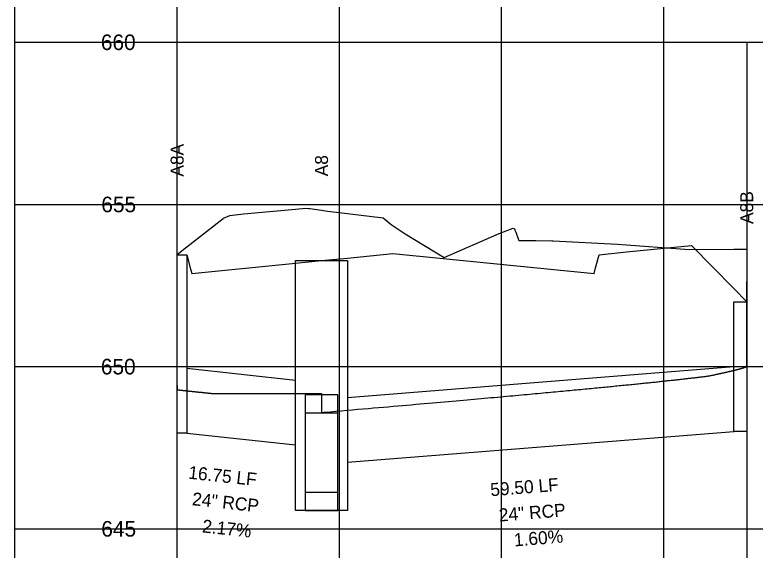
# Model space of a CAD drawing. Extents: x 2252703 to 2264864, y 13787568 to 13790989.
# Drawn here: x 2264413.7 to 2264527.7, y 13788382.5 to 13788465 of the extents above; entities that cross this region are included whole.
import ezdxf

# ---------------------------------------------------------------- set-up
doc = ezdxf.new("R2010")
doc.units = 0
for name, color, linetype in [('blank4', 7, 'Continuous'), ('BORD_grid_bottom_major_5int', 7, 'Continuous'), ('D_DRN_PROF_HGL', 7, 'Continuous'), ('D_PROF_1', 7, 'Continuous'), ('D_PROF_NOTES_1', 7, 'Continuous'), ('Default', 7, 'Continuous'), ('Drain_PipeInside', 7, 'Continuous'), ('E_Terrain', 7, 'Continuous'), ('Inlet', 7, 'Continuous'), ('z - Construction', 7, 'Continuous')]:
    doc.layers.add(name, color=color, linetype=linetype)

msp = doc.modelspace()

# ---------------------------------------------------------------- linework, layer by layer
at = {"layer": 'blank4'}
msp.add_lwpolyline([(2264438.67, 13788360.79), (2264438.67, 13788460.79), (2264526.42, 13788460.79), (2264526.42, 13788360.79)], close=True, dxfattribs=at)
at = {"layer": 'BORD_grid_bottom_major_5int'}
for p, q in [((2264413.67, 13788310.79), (2264413.67, 13788610.79)), ((2264438.67, 13788310.79), (2264438.67, 13788610.79)), ((2264463.67, 13788310.79), (2264463.67, 13788610.79)), ((2264488.67, 13788310.79), (2264488.67, 13788610.79)), ((2264513.67, 13788310.79), (2264513.67, 13788610.79)), ((2264413.67, 13788460.79), (2264763.67, 13788460.79)), ((2264413.67, 13788435.79), (2264763.67, 13788435.79)), ((2264413.67, 13788410.79), (2264763.67, 13788410.79)), ((2264413.67, 13788385.79), (2264763.67, 13788385.79))]:
    msp.add_line(p, q, dxfattribs=at)
at = {"layer": 'D_DRN_PROF_HGL'}
msp.add_line((2264460.92, 13788406.67), (2264460.92, 13788403.73), dxfattribs=at)
for points in [[(2264460.92, 13788403.73), (2264461.33, 13788403.76), (2264462.24, 13788403.84), (2264463.13, 13788403.92), (2264464, 13788403.99), (2264464.86, 13788404.07), (2264465.7, 13788404.14), (2264466.53, 13788404.21), (2264467.34, 13788404.28), (2264468.14, 13788404.35), (2264468.93, 13788404.42), (2264469.7, 13788404.48), (2264470.46, 13788404.55), (2264471.2, 13788404.61), (2264471.94, 13788404.68), (2264472.66, 13788404.74), (2264473.37, 13788404.8), (2264474.06, 13788404.86), (2264474.75, 13788404.92), (2264475.43, 13788404.98), (2264476.09, 13788405.04), (2264476.75, 13788405.1), (2264477.39, 13788405.15), (2264478.03, 13788405.21), (2264478.65, 13788405.27), (2264479.27, 13788405.32), (2264479.88, 13788405.37), (2264480.47, 13788405.43), (2264481.06, 13788405.48), (2264481.64, 13788405.53), (2264482.22, 13788405.58), (2264482.78, 13788405.63), (2264483.34, 13788405.68), (2264483.89, 13788405.73), (2264484.43, 13788405.78), (2264484.96, 13788405.82), (2264485.49, 13788405.87), (2264486, 13788405.92), (2264486.52, 13788405.96), (2264487.02, 13788406.01), (2264487.52, 13788406.05), (2264488.01, 13788406.1), (2264488.49, 13788406.14), (2264488.97, 13788406.19), (2264489.44, 13788406.23), (2264489.91, 13788406.27), (2264490.37, 13788406.31), (2264490.82, 13788406.35), (2264491.27, 13788406.39), (2264491.72, 13788406.44), (2264492.15, 13788406.48), (2264492.58, 13788406.51), (2264493.01, 13788406.55), (2264493.43, 13788406.59), (2264493.85, 13788406.63), (2264494.26, 13788406.67), (2264494.66, 13788406.71), (2264495.06, 13788406.74), (2264495.46, 13788406.78), (2264495.85, 13788406.82), (2264496.23, 13788406.85), (2264496.62, 13788406.89), (2264496.99, 13788406.92), (2264497.36, 13788406.96), (2264497.73, 13788406.99), (2264498.1, 13788407.03), (2264498.46, 13788407.06), (2264498.81, 13788407.09), (2264499.16, 13788407.13), (2264499.51, 13788407.16), (2264499.85, 13788407.19), (2264500.19, 13788407.22), (2264500.52, 13788407.26), (2264500.86, 13788407.29), (2264501.18, 13788407.32), (2264501.51, 13788407.35), (2264501.83, 13788407.38), (2264502.14, 13788407.41), (2264502.46, 13788407.44), (2264502.77, 13788407.47), (2264503.07, 13788407.5), (2264503.37, 13788407.53), (2264503.67, 13788407.56), (2264503.97, 13788407.59), (2264504.26, 13788407.61), (2264504.55, 13788407.64), (2264504.83, 13788407.67), (2264505.12, 13788407.7), (2264505.4, 13788407.72), (2264505.67, 13788407.75), (2264505.95, 13788407.78), (2264506.22, 13788407.81), (2264506.49, 13788407.83), (2264506.75, 13788407.86), (2264507.01, 13788407.88), (2264507.27, 13788407.91), (2264507.53, 13788407.94), (2264507.78, 13788407.96), (2264508.03, 13788407.99), (2264508.28, 13788408.01), (2264508.52, 13788408.03), (2264508.77, 13788408.06), (2264509.01, 13788408.08), (2264509.24, 13788408.11), (2264509.48, 13788408.13), (2264509.71, 13788408.15), (2264509.94, 13788408.18), (2264510.17, 13788408.2), (2264510.39, 13788408.22), (2264510.61, 13788408.25), (2264510.84, 13788408.27), (2264511.05, 13788408.29), (2264511.27, 13788408.31), (2264511.48, 13788408.34), (2264511.69, 13788408.36), (2264511.9, 13788408.38), (2264512.11, 13788408.4), (2264512.31, 13788408.42), (2264512.51, 13788408.44), (2264512.71, 13788408.47), (2264512.91, 13788408.49), (2264513.11, 13788408.51), (2264513.3, 13788408.53), (2264513.49, 13788408.55), (2264513.68, 13788408.57), (2264513.87, 13788408.59), (2264514.05, 13788408.61), (2264514.24, 13788408.63), (2264514.42, 13788408.65), (2264514.6, 13788408.67), (2264514.78, 13788408.69), (2264514.95, 13788408.7), (2264515.13, 13788408.72), (2264515.3, 13788408.74), (2264515.47, 13788408.76), (2264515.64, 13788408.78), (2264515.8, 13788408.8), (2264515.97, 13788408.82), (2264516.13, 13788408.83), (2264516.29, 13788408.85), (2264516.45, 13788408.87), (2264516.61, 13788408.89), (2264516.76, 13788408.9), (2264516.92, 13788408.92), (2264517.07, 13788408.94), (2264517.22, 13788408.96), (2264517.37, 13788408.97), (2264517.52, 13788408.99), (2264517.67, 13788409.01), (2264517.81, 13788409.02), (2264517.95, 13788409.04), (2264518.09, 13788409.06), (2264518.23, 13788409.07), (2264518.37, 13788409.09), (2264518.51, 13788409.1), (2264518.64, 13788409.12), (2264518.78, 13788409.14), (2264518.91, 13788409.15), (2264519.04, 13788409.17), (2264519.17, 13788409.18), (2264519.3, 13788409.2), (2264519.42, 13788409.21), (2264519.55, 13788409.23), (2264519.67, 13788409.24), (2264519.79, 13788409.26), (2264519.91, 13788409.27), (2264520.03, 13788409.29), (2264520.15, 13788409.3), (2264520.26, 13788409.31), (2264520.38, 13788409.33), (2264520.49, 13788409.35), (2264520.61, 13788409.37), (2264520.72, 13788409.39), (2264520.83, 13788409.42), (2264520.93, 13788409.44), (2264521.04, 13788409.46), (2264521.15, 13788409.48), (2264521.25, 13788409.5), (2264521.35, 13788409.53), (2264521.46, 13788409.55), (2264521.56, 13788409.57), (2264521.66, 13788409.59), (2264521.75, 13788409.61), (2264521.85, 13788409.63), (2264521.95, 13788409.65), (2264522.04, 13788409.67), (2264522.13, 13788409.69), (2264522.23, 13788409.71), (2264522.32, 13788409.73), (2264522.41, 13788409.75), (2264522.5, 13788409.77), (2264522.58, 13788409.79), (2264522.67, 13788409.81), (2264522.75, 13788409.83), (2264522.84, 13788409.84), (2264522.92, 13788409.86), (2264523, 13788409.88), (2264523.08, 13788409.9), (2264523.16, 13788409.92), (2264523.24, 13788409.93), (2264523.32, 13788409.95), (2264523.39, 13788409.97), (2264523.47, 13788409.98), (2264523.54, 13788410), (2264523.62, 13788410.02), (2264523.69, 13788410.03), (2264523.76, 13788410.05), (2264523.83, 13788410.07), (2264523.9, 13788410.08), (2264523.97, 13788410.1), (2264524.03, 13788410.11), (2264524.1, 13788410.13), (2264524.16, 13788410.15), (2264524.23, 13788410.16), (2264524.29, 13788410.18), (2264524.35, 13788410.19), (2264524.41, 13788410.2), (2264524.47, 13788410.22), (2264524.53, 13788410.23), (2264524.59, 13788410.25), (2264524.64, 13788410.26), (2264524.7, 13788410.28), (2264524.75, 13788410.29), (2264524.81, 13788410.3), (2264524.86, 13788410.32), (2264524.91, 13788410.33), (2264524.96, 13788410.34), (2264525.01, 13788410.36), (2264525.06, 13788410.37), (2264525.11, 13788410.38), (2264525.16, 13788410.39), (2264525.2, 13788410.41), (2264525.25, 13788410.42), (2264525.29, 13788410.43), (2264525.34, 13788410.44), (2264525.38, 13788410.45), (2264525.42, 13788410.47), (2264525.46, 13788410.48), (2264525.5, 13788410.49), (2264525.54, 13788410.5), (2264525.58, 13788410.51), (2264525.61, 13788410.52), (2264525.65, 13788410.53), (2264525.69, 13788410.54), (2264525.72, 13788410.55), (2264525.75, 13788410.56), (2264525.79, 13788410.58), (2264525.82, 13788410.59), (2264525.85, 13788410.6), (2264525.88, 13788410.61), (2264525.91, 13788410.61), (2264525.94, 13788410.62), (2264525.97, 13788410.63), (2264525.99, 13788410.64), (2264526.02, 13788410.65), (2264526.04, 13788410.66), (2264526.07, 13788410.67), (2264526.09, 13788410.68), (2264526.11, 13788410.69), (2264526.14, 13788410.7), (2264526.16, 13788410.7), (2264526.18, 13788410.71), (2264526.2, 13788410.72), (2264526.21, 13788410.73), (2264526.23, 13788410.74), (2264526.25, 13788410.74), (2264526.27, 13788410.75), (2264526.28, 13788410.76), (2264526.3, 13788410.77), (2264526.31, 13788410.77), (2264526.32, 13788410.78), (2264526.33, 13788410.79), (2264526.35, 13788410.79), (2264526.36, 13788410.8), (2264526.37, 13788410.81), (2264526.37, 13788410.81), (2264526.38, 13788410.82), (2264526.39, 13788410.83), (2264526.4, 13788410.83), (2264526.4, 13788410.84), (2264526.41, 13788410.84), (2264526.41, 13788410.85), (2264526.42, 13788410.86), (2264526.42, 13788410.86), (2264526.42, 13788410.87), (2264526.42, 13788410.87), (2264526.42, 13788410.88), (2264526.42, 13788423.89)], [(2264438.67, 13788407.9), (2264438.67, 13788407.22), (2264438.71, 13788407.22), (2264438.76, 13788407.21), (2264438.8, 13788407.21), (2264438.85, 13788407.21), (2264438.89, 13788407.2), (2264438.94, 13788407.2), (2264438.98, 13788407.19), (2264439.03, 13788407.19), (2264439.07, 13788407.18), (2264439.11, 13788407.18), (2264439.16, 13788407.17), (2264439.2, 13788407.17), (2264439.25, 13788407.16), (2264439.29, 13788407.16), (2264439.34, 13788407.15), (2264439.38, 13788407.15), (2264439.43, 13788407.14), (2264439.47, 13788407.14), (2264439.51, 13788407.14), (2264439.56, 13788407.13), (2264439.6, 13788407.13), (2264439.65, 13788407.12), (2264439.69, 13788407.12), (2264439.74, 13788407.11), (2264439.78, 13788407.11), (2264439.83, 13788407.1), (2264439.87, 13788407.1), (2264439.92, 13788407.09), (2264439.96, 13788407.09), (2264440.01, 13788407.08), (2264440.05, 13788407.08), (2264440.09, 13788407.07), (2264440.14, 13788407.07), (2264440.18, 13788407.07), (2264440.23, 13788407.06), (2264440.27, 13788407.06), (2264440.32, 13788407.05), (2264440.36, 13788407.05), (2264440.41, 13788407.04), (2264440.45, 13788407.04), (2264440.5, 13788407.03), (2264440.54, 13788407.03), (2264440.59, 13788407.02), (2264440.63, 13788407.02), (2264440.68, 13788407.01), (2264440.72, 13788407.01), (2264440.77, 13788407), (2264440.81, 13788407), (2264440.85, 13788407), (2264440.9, 13788406.99), (2264440.94, 13788406.99), (2264440.99, 13788406.98), (2264441.03, 13788406.98), (2264441.08, 13788406.97), (2264441.12, 13788406.97), (2264441.17, 13788406.96), (2264441.21, 13788406.96), (2264441.26, 13788406.95), (2264441.3, 13788406.95), (2264441.35, 13788406.94), (2264441.39, 13788406.94), (2264441.44, 13788406.93), (2264441.48, 13788406.93), (2264441.53, 13788406.92), (2264441.57, 13788406.92), (2264441.62, 13788406.92), (2264441.66, 13788406.91), (2264441.71, 13788406.91), (2264441.75, 13788406.9), (2264441.8, 13788406.9), (2264441.84, 13788406.89), (2264441.88, 13788406.89), (2264441.93, 13788406.88), (2264441.97, 13788406.88), (2264442.02, 13788406.87), (2264442.06, 13788406.87), (2264442.11, 13788406.86), (2264442.15, 13788406.86), (2264442.2, 13788406.85), (2264442.24, 13788406.85), (2264442.29, 13788406.84), (2264442.33, 13788406.84), (2264442.38, 13788406.84), (2264442.42, 13788406.83), (2264442.47, 13788406.83), (2264442.51, 13788406.82), (2264442.56, 13788406.82), (2264442.6, 13788406.81), (2264442.65, 13788406.81), (2264442.69, 13788406.8), (2264442.74, 13788406.8), (2264442.78, 13788406.79), (2264442.83, 13788406.79), (2264442.87, 13788406.78), (2264442.92, 13788406.78), (2264442.96, 13788406.77), (2264443.01, 13788406.77), (2264443.05, 13788406.76), (2264443.1, 13788406.76), (2264443.14, 13788406.75), (2264443.19, 13788406.75), (2264443.23, 13788406.75), (2264443.28, 13788406.74), (2264443.32, 13788406.74), (2264443.37, 13788406.73), (2264443.41, 13788406.73), (2264443.46, 13788406.72), (2264443.5, 13788406.72), (2264443.55, 13788406.71), (2264443.59, 13788406.71), (2264443.64, 13788406.7), (2264443.68, 13788406.7), (2264443.73, 13788406.69), (2264443.77, 13788406.69), (2264443.82, 13788406.68), (2264443.86, 13788406.68), (2264443.91, 13788406.67), (2264443.95, 13788406.67), (2264444, 13788406.66), (2264444.04, 13788406.66), (2264444.09, 13788406.65), (2264444.13, 13788406.65), (2264444.18, 13788406.65), (2264444.22, 13788406.65), (2264444.27, 13788406.65), (2264444.31, 13788406.65), (2264444.36, 13788406.65), (2264444.4, 13788406.65), (2264444.45, 13788406.65), (2264444.49, 13788406.65), (2264444.54, 13788406.65), (2264444.58, 13788406.65), (2264444.63, 13788406.65), (2264444.67, 13788406.65), (2264444.72, 13788406.65), (2264444.76, 13788406.65), (2264444.81, 13788406.65), (2264444.85, 13788406.65), (2264444.9, 13788406.65), (2264444.94, 13788406.65), (2264444.99, 13788406.65), (2264445.03, 13788406.65), (2264445.08, 13788406.65), (2264445.12, 13788406.65), (2264445.17, 13788406.65), (2264445.21, 13788406.65), (2264445.26, 13788406.65), (2264445.3, 13788406.65), (2264445.35, 13788406.65), (2264445.39, 13788406.65), (2264445.44, 13788406.65), (2264445.48, 13788406.65), (2264445.53, 13788406.65), (2264445.58, 13788406.65), (2264445.62, 13788406.65), (2264445.67, 13788406.65), (2264445.71, 13788406.65), (2264445.76, 13788406.65), (2264445.8, 13788406.65), (2264445.85, 13788406.65), (2264445.89, 13788406.65), (2264445.94, 13788406.65), (2264445.98, 13788406.65), (2264446.03, 13788406.65), (2264446.07, 13788406.65), (2264446.12, 13788406.65), (2264446.16, 13788406.65), (2264446.21, 13788406.65), (2264446.25, 13788406.65), (2264446.3, 13788406.65), (2264446.34, 13788406.65), (2264446.39, 13788406.65), (2264446.43, 13788406.65), (2264446.48, 13788406.65), (2264446.52, 13788406.65), (2264446.57, 13788406.65), (2264446.61, 13788406.65), (2264446.66, 13788406.65), (2264446.71, 13788406.65), (2264446.75, 13788406.65), (2264446.8, 13788406.65), (2264446.84, 13788406.65), (2264446.89, 13788406.65), (2264446.93, 13788406.65), (2264446.98, 13788406.65), (2264447.02, 13788406.65), (2264447.07, 13788406.65), (2264447.11, 13788406.65), (2264447.16, 13788406.65), (2264447.2, 13788406.65), (2264447.25, 13788406.65), (2264447.29, 13788406.65), (2264447.34, 13788406.65), (2264447.38, 13788406.65), (2264447.43, 13788406.65), (2264447.47, 13788406.65), (2264447.52, 13788406.65), (2264447.57, 13788406.65), (2264447.61, 13788406.65), (2264447.66, 13788406.65), (2264447.7, 13788406.65), (2264447.75, 13788406.65), (2264447.79, 13788406.65), (2264447.84, 13788406.65), (2264447.88, 13788406.65), (2264447.93, 13788406.65), (2264447.97, 13788406.65), (2264448.02, 13788406.65), (2264448.06, 13788406.65), (2264448.11, 13788406.65), (2264448.15, 13788406.65), (2264448.2, 13788406.65), (2264448.24, 13788406.65), (2264448.29, 13788406.65), (2264448.34, 13788406.65), (2264448.38, 13788406.65), (2264448.43, 13788406.66), (2264448.47, 13788406.66), (2264448.52, 13788406.66), (2264448.56, 13788406.66), (2264448.61, 13788406.66), (2264448.65, 13788406.66), (2264448.7, 13788406.66), (2264448.74, 13788406.66), (2264448.79, 13788406.66), (2264448.83, 13788406.66), (2264448.88, 13788406.66), (2264448.92, 13788406.66), (2264448.97, 13788406.66), (2264449.02, 13788406.66), (2264449.06, 13788406.66), (2264449.11, 13788406.66), (2264449.15, 13788406.66), (2264449.2, 13788406.66), (2264449.24, 13788406.66), (2264449.29, 13788406.66), (2264449.33, 13788406.66), (2264449.38, 13788406.66), (2264449.42, 13788406.66), (2264449.47, 13788406.66), (2264449.51, 13788406.66), (2264449.56, 13788406.66), (2264449.61, 13788406.66), (2264449.65, 13788406.66), (2264449.7, 13788406.66), (2264449.74, 13788406.66), (2264449.79, 13788406.66), (2264449.83, 13788406.66), (2264449.88, 13788406.66), (2264449.92, 13788406.66), (2264449.97, 13788406.66), (2264450.01, 13788406.66), (2264450.06, 13788406.66), (2264450.11, 13788406.66), (2264450.15, 13788406.66), (2264450.2, 13788406.66), (2264450.24, 13788406.66), (2264450.29, 13788406.66), (2264450.33, 13788406.66), (2264450.38, 13788406.66), (2264450.42, 13788406.66), (2264450.47, 13788406.66), (2264450.51, 13788406.66), (2264450.56, 13788406.66), (2264450.6, 13788406.66), (2264450.65, 13788406.66), (2264450.7, 13788406.66), (2264450.74, 13788406.66), (2264450.79, 13788406.66), (2264450.83, 13788406.66), (2264450.88, 13788406.66), (2264450.92, 13788406.66), (2264450.97, 13788406.66), (2264451.01, 13788406.66), (2264451.06, 13788406.66), (2264451.11, 13788406.66), (2264451.15, 13788406.66), (2264451.2, 13788406.66), (2264451.24, 13788406.66), (2264451.29, 13788406.66), (2264451.33, 13788406.66), (2264451.38, 13788406.66), (2264451.42, 13788406.66), (2264451.47, 13788406.66), (2264451.51, 13788406.66), (2264451.56, 13788406.66), (2264451.61, 13788406.66), (2264451.65, 13788406.66), (2264451.7, 13788406.66), (2264451.74, 13788406.66), (2264451.79, 13788406.66), (2264451.83, 13788406.66), (2264451.88, 13788406.66), (2264451.92, 13788406.66), (2264451.97, 13788406.66), (2264452.01, 13788406.66), (2264452.06, 13788406.66), (2264452.11, 13788406.66), (2264452.15, 13788406.66), (2264452.2, 13788406.66), (2264452.24, 13788406.66), (2264452.29, 13788406.66), (2264452.33, 13788406.66), (2264452.38, 13788406.66), (2264452.42, 13788406.66), (2264452.47, 13788406.66), (2264452.52, 13788406.66), (2264452.56, 13788406.66), (2264452.61, 13788406.66), (2264452.65, 13788406.66), (2264452.7, 13788406.66), (2264452.74, 13788406.66), (2264452.79, 13788406.66), (2264452.83, 13788406.66), (2264452.88, 13788406.66), (2264452.93, 13788406.66), (2264452.97, 13788406.66), (2264453.02, 13788406.66), (2264453.06, 13788406.66), (2264453.11, 13788406.66), (2264453.15, 13788406.66), (2264453.2, 13788406.66), (2264453.24, 13788406.66), (2264453.29, 13788406.66), (2264453.34, 13788406.66), (2264453.38, 13788406.66), (2264453.43, 13788406.66), (2264453.47, 13788406.66), (2264453.52, 13788406.66), (2264453.56, 13788406.66), (2264453.61, 13788406.66), (2264453.65, 13788406.66), (2264453.7, 13788406.66), (2264453.75, 13788406.66), (2264453.79, 13788406.66), (2264453.84, 13788406.66), (2264453.88, 13788406.66), (2264453.93, 13788406.66), (2264453.97, 13788406.66), (2264454.02, 13788406.66), (2264454.07, 13788406.66), (2264454.11, 13788406.66), (2264454.16, 13788406.66), (2264454.2, 13788406.66), (2264454.25, 13788406.66), (2264454.29, 13788406.66), (2264454.34, 13788406.66), (2264454.38, 13788406.66), (2264454.43, 13788406.66), (2264454.48, 13788406.66), (2264454.52, 13788406.66), (2264454.57, 13788406.66), (2264454.61, 13788406.67), (2264454.66, 13788406.67), (2264454.7, 13788406.67), (2264454.75, 13788406.67), (2264454.79, 13788406.67), (2264454.84, 13788406.67), (2264454.89, 13788406.67), (2264454.93, 13788406.67), (2264454.98, 13788406.67), (2264455.02, 13788406.67), (2264455.07, 13788406.67), (2264455.11, 13788406.67), (2264455.16, 13788406.67), (2264455.21, 13788406.67), (2264455.25, 13788406.67), (2264455.3, 13788406.67), (2264455.34, 13788406.67), (2264455.39, 13788406.67), (2264455.43, 13788406.67), (2264455.48, 13788406.67), (2264455.53, 13788406.67), (2264455.57, 13788406.67), (2264455.62, 13788406.67), (2264455.66, 13788406.67), (2264455.71, 13788406.67), (2264455.75, 13788406.67), (2264455.8, 13788406.67), (2264455.84, 13788406.67), (2264455.89, 13788406.67), (2264455.94, 13788406.67), (2264455.98, 13788406.67), (2264456.03, 13788406.67), (2264456.07, 13788406.67), (2264456.12, 13788406.67), (2264456.16, 13788406.67), (2264456.21, 13788406.67), (2264456.26, 13788406.67), (2264456.3, 13788406.67), (2264456.35, 13788406.67), (2264456.39, 13788406.67), (2264456.44, 13788406.67), (2264456.48, 13788406.67), (2264456.53, 13788406.67), (2264456.58, 13788406.67), (2264456.62, 13788406.67), (2264456.67, 13788406.67), (2264456.71, 13788406.67), (2264456.76, 13788406.67), (2264456.8, 13788406.67), (2264456.85, 13788406.67), (2264456.9, 13788406.67), (2264456.94, 13788406.67), (2264456.99, 13788406.67), (2264457.03, 13788406.67), (2264457.08, 13788406.67), (2264457.12, 13788406.67), (2264457.17, 13788406.67), (2264457.22, 13788406.67), (2264457.26, 13788406.67), (2264457.31, 13788406.67), (2264457.35, 13788406.67), (2264457.4, 13788406.67), (2264457.44, 13788406.67), (2264457.49, 13788406.67), (2264457.54, 13788406.67), (2264457.58, 13788406.67), (2264457.63, 13788406.67), (2264457.67, 13788406.67), (2264457.72, 13788406.67), (2264457.76, 13788406.67), (2264457.81, 13788406.67), (2264457.86, 13788406.67), (2264457.9, 13788406.67), (2264457.95, 13788406.67), (2264457.99, 13788406.67), (2264458.04, 13788406.67), (2264458.08, 13788406.67), (2264458.13, 13788406.67), (2264458.18, 13788406.67), (2264458.22, 13788406.67), (2264458.27, 13788406.67), (2264458.31, 13788406.67), (2264458.36, 13788406.67), (2264458.4, 13788406.67), (2264458.45, 13788406.67), (2264458.5, 13788406.67), (2264458.54, 13788406.67), (2264458.59, 13788406.67), (2264458.63, 13788406.67), (2264458.68, 13788406.67), (2264458.72, 13788406.67), (2264458.77, 13788406.67), (2264458.82, 13788406.67), (2264458.86, 13788406.67), (2264458.91, 13788406.67), (2264458.95, 13788406.67), (2264459, 13788406.67), (2264459.04, 13788406.67), (2264459.09, 13788406.67), (2264459.14, 13788406.67), (2264459.18, 13788406.67), (2264459.23, 13788406.67), (2264459.27, 13788406.67), (2264459.32, 13788406.67), (2264459.36, 13788406.67), (2264459.41, 13788406.67), (2264459.46, 13788406.67), (2264459.5, 13788406.67), (2264459.55, 13788406.67), (2264459.59, 13788406.67), (2264459.64, 13788406.67), (2264459.69, 13788406.67), (2264459.73, 13788406.67), (2264459.78, 13788406.67), (2264459.82, 13788406.67), (2264459.87, 13788406.67), (2264459.91, 13788406.67), (2264459.96, 13788406.67), (2264460.01, 13788406.67), (2264460.05, 13788406.67), (2264460.1, 13788406.67), (2264460.14, 13788406.67), (2264460.19, 13788406.67), (2264460.23, 13788406.67), (2264460.28, 13788406.67), (2264460.33, 13788406.67), (2264460.37, 13788406.67), (2264460.42, 13788406.67), (2264460.46, 13788406.67), (2264460.51, 13788406.67), (2264460.56, 13788406.67), (2264460.6, 13788406.67), (2264460.65, 13788406.67), (2264460.69, 13788406.67), (2264460.74, 13788406.67), (2264460.78, 13788406.67), (2264460.83, 13788406.67), (2264460.88, 13788406.67), (2264460.92, 13788406.67)]]:
    msp.add_lwpolyline(points, dxfattribs=at)
at = {"layer": 'D_PROF_1'}
msp.add_lwpolyline([(2264440.17, 13788428.04), (2264440.17, 13788428.04), (2264440.17, 13788428.04), (2264440.69, 13788426.02), (2264440.92, 13788425.13), (2264456.92, 13788426.73), (2264456.92, 13788426.73), (2264460.92, 13788427.13), (2264460.92, 13788427.13), (2264464.92, 13788427.53), (2264464.92, 13788427.53), (2264471.92, 13788428.23), (2264502.92, 13788425.13), (2264503.15, 13788426.02), (2264503.67, 13788428.04), (2264507.92, 13788428.47), (2264517.92, 13788429.47), (2264524.42, 13788422.83), (2264524.42, 13788422.83), (2264526.42, 13788420.79), (2264526.42, 13788420.79)], dxfattribs=at)
at = {"layer": 'Drain_PipeInside'}
for p, q in [((2264440.17, 13788410.54), (2264456.92, 13788408.73)), ((2264464.92, 13788406.04), (2264524.42, 13788410.8)), ((2264440.17, 13788400.54), (2264456.92, 13788398.73)), ((2264464.92, 13788396.04), (2264524.42, 13788400.8))]:
    msp.add_line(p, q, dxfattribs=at)
for points in [[(2264458.42, 13788391.42), (2264463.42, 13788391.42), (2264463.42, 13788406.42), (2264458.42, 13788406.42)], [(2264458.42, 13788388.63), (2264463.42, 13788388.63), (2264463.42, 13788403.63), (2264458.42, 13788403.63)]]:
    msp.add_lwpolyline(points, close=True, dxfattribs=at)
at = {"layer": 'E_Terrain'}
msp.add_lwpolyline([(2264438.67, 13788428.09), (2264440.17, 13788429.26), (2264440.17, 13788429.26), (2264445.77, 13788433.65), (2264445.83, 13788433.67), (2264446.78, 13788434.1), (2264448.92, 13788434.35), (2264449.52, 13788434.38), (2264456.92, 13788435.06), (2264456.92, 13788435.06), (2264458.5, 13788435.21), (2264458.99, 13788435.17), (2264459.14, 13788435.17), (2264460.92, 13788434.89), (2264460.92, 13788434.89), (2264461.84, 13788434.74), (2264464.92, 13788434.38), (2264464.92, 13788434.38), (2264470.42, 13788433.73), (2264471.64, 13788432.7), (2264471.81, 13788432.58), (2264473.83, 13788431.27), (2264479.81, 13788427.6), (2264488.3, 13788431.31), (2264490.44, 13788432.14), (2264490.65, 13788432.01), (2264490.66, 13788432), (2264490.68, 13788431.93), (2264490.68, 13788431.93), (2264490.68, 13788431.92), (2264490.72, 13788431.84), (2264490.76, 13788431.72), (2264490.77, 13788431.71), (2264490.77, 13788431.7), (2264490.84, 13788431.52), (2264490.95, 13788431.24), (2264490.95, 13788431.22), (2264490.96, 13788431.2), (2264491.12, 13788430.79), (2264491.17, 13788430.67), (2264491.34, 13788430.21), (2264493.91, 13788430.22), (2264496.42, 13788430.17), (2264496.61, 13788430.16), (2264506.52, 13788429.65), (2264517.55, 13788428.83), (2264524.42, 13788428.89), (2264524.42, 13788428.89), (2264526.42, 13788428.91)], dxfattribs=at)
at = {"layer": 'Inlet'}
for points in [[(2264438.67, 13788428.04), (2264440.17, 13788428.04), (2264440.17, 13788400.54), (2264438.67, 13788400.54)], [(2264456.92, 13788427.13), (2264464.92, 13788427.13), (2264464.92, 13788388.63), (2264456.92, 13788388.63)], [(2264524.42, 13788420.8), (2264526.42, 13788420.8), (2264526.42, 13788400.8), (2264524.42, 13788400.8)]]:
    msp.add_lwpolyline(points, close=True, dxfattribs=at)
at = {"layer": 'z - Construction'}
for p, q in [((2264438.67, 13788435.79), (2264526.42, 13788435.79)), ((2264438.67, 13788410.79), (2264526.42, 13788410.79)), ((2264438.67, 13788385.79), (2264526.42, 13788385.79))]:
    msp.add_line(p, q, dxfattribs=at)

# ---------------------------------------------------------------- texts
at = {"layer": 'D_PROF_NOTES_1'}
for s, rotation, p in [('A8A', 90, (2264439.67, 13788440.08)), ('A8', 90, (2264461.92, 13788440.13)), ('A8B', 90, (2264527.42, 13788432.78)), ('16.75 LF', 353.8157, (2264440.33, 13788393.53)), ('59.50 LF', 4.5739, (2264487, 13788390.81)), ('24" RCP', 353.8157, (2264440.91, 13788389.45)), ('24" RCP', 4.5739, (2264488.32, 13788386.9)), ('2.17%', 353.8157, (2264442.47, 13788385.25)), ('1.60%', 4.5739, (2264490.64, 13788383.07))]:
    msp.add_text(s, height=2, rotation=rotation, dxfattribs=at).set_placement(p)
at = {"layer": 'Default'}
for s, p in [('660', (2264426.93, 13788459.59)), ('655', (2264427, 13788434.59)), ('650', (2264426.93, 13788409.59)), ('645', (2264427, 13788384.59))]:
    msp.add_text(s, height=2.4, dxfattribs=at).set_placement(p)

doc.saveas('drawing.dxf')
